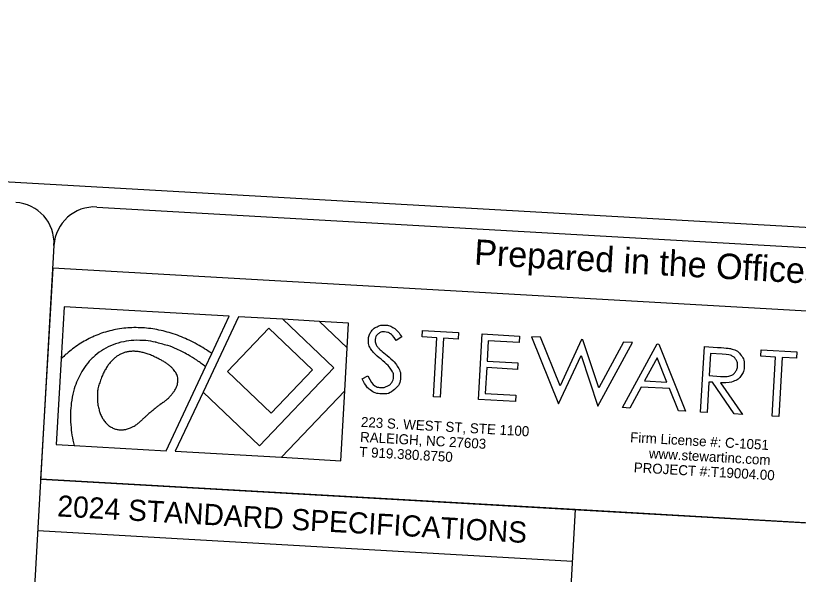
# Model space of a CAD drawing. Extents: x 2601627 to 2606907, y 616646 to 620530.
# Drawn here: x 2604538 to 2605115, y 617426 to 617838 of the extents above; entities that cross this region are included whole.
import ezdxf

# ---------------------------------------------------------------- set-up
doc = ezdxf.new("R2010")
doc.units = 0
doc.layers.add('Sheet Title CELL', color=7, linetype='Continuous')
doc.layers.add('Stewart Logo', color=7, linetype='Continuous')

msp = doc.modelspace()

# ---------------------------------------------------------------- linework, layer by layer
at = {"layer": 'Sheet Title CELL'}
for p, q in [((2602382.68, 617837.86), (2606635.79, 617595.63)), ((2604598.24, 617696.65), (2605451.86, 617648.03)), ((2604566.58, 617668.41), (2604539.29, 617189.18)), ((2604950.78, 617473.73), (2604556.77, 617496.18)), ((2604950.78, 617473.73), (2604931.59, 617136.79)), ((2605470.29, 617444.12), (2604950.78, 617473.73)), ((2604948.61, 617435.52), (2604554.6, 617458)), ((2604835.09, 617442.02), (2604835.09, 617442.02))]:
    msp.add_line(p, q, dxfattribs=at)
msp.add_lwpolyline([(2604556.77, 617496.18), (2605470.29, 617444.15), (2605479.15, 617599.69), (2604565.63, 617651.72)], close=True, dxfattribs=at)
for centre, start, end in [((2604536.65, 617670.24), 356.74026, 86.74026), ((2604596.55, 617666.83), 86.74026, 176.74026)]:
    msp.add_arc(centre, 30, start, end, dxfattribs=at)
at = {"layer": 'Stewart Logo'}
for p, q in [((2604574.08, 617623.18), (2604571.9, 617584.86)), ((2604695.75, 617616.25), (2604574.08, 617623.18)), ((2604702.53, 617615.87), (2604676.43, 617560.32)), ((2604682.83, 617588.75), (2604695.75, 617616.25)), ((2604735.34, 617614), (2604702.53, 617615.87)), ((2604735.34, 617614), (2604772.85, 617578.17)), ((2604762.32, 617612.46), (2604735.34, 617614)), ((2604772.85, 617578.17), (2604735.34, 617614)), ((2604783.73, 617611.24), (2604762.32, 617612.46)), ((2604762.32, 617612.46), (2604782.7, 617593)), ((2604782.7, 617593), (2604762.32, 617612.46)), ((2604782.7, 617593), (2604783.73, 617611.24)), ((2604600.3, 617603.21), (2604600.14, 617603.06)), ((2604606.3, 617605.1), (2604606.05, 617605.04)), ((2604642.37, 617606.42), (2604642.42, 617606.42)), ((2604641.35, 617597.05), (2604641.59, 617597.15)), ((2604925.07, 617600.76), (2604918.5, 617601.14)), ((2604918.5, 617601.14), (2604938.44, 617551.61)), ((2604939.5, 617565.07), (2604925.07, 617600.76)), ((2604955.38, 617599.04), (2604939.5, 617565.07)), ((2604956.32, 617598.98), (2604955.38, 617599.04)), ((2604968, 617563.45), (2604956.32, 617598.98)), ((2604967.45, 617549.96), (2604992.96, 617596.89)), ((2604986.39, 617597.27), (2604968, 617563.45)), ((2604992.96, 617596.89), (2604986.39, 617597.27)), ((2604672.08, 617595.55), (2604672.11, 617595.53)), ((2604780.89, 617561.22), (2604782.7, 617593)), ((2604678.25, 617578.99), (2604682.83, 617588.75)), ((2604938.44, 617551.61), (2604955.18, 617587.29)), ((2604955.18, 617587.29), (2604967.45, 617549.96)), ((2604571.9, 617584.86), (2604568.3, 617521.74)), ((2604649.19, 617517.14), (2604678.25, 617578.99)), ((2604772.85, 617578.17), (2604717.93, 617520.68)), ((2604717.93, 617520.68), (2604772.85, 617578.17)), ((2604726.61, 617544.85), (2604757.09, 617576.76)), ((2604676.43, 617560.32), (2604655.97, 617516.75)), ((2604717.93, 617520.68), (2604676.43, 617560.32)), ((2604676.43, 617560.32), (2604717.93, 617520.68)), ((2604780.89, 617561.22), (2604734.16, 617512.3)), ((2604734.16, 617512.3), (2604780.89, 617561.22)), ((2604777.96, 617509.8), (2604780.89, 617561.22)), ((2604568.3, 617521.74), (2604581.39, 617521)), ((2604581.39, 617521), (2604649.19, 617517.14)), ((2604655.97, 617516.75), (2604734.16, 617512.3)), ((2604734.16, 617512.3), (2604777.96, 617509.8))]:
    msp.add_line(p, q, dxfattribs=at)
for points in [[(2604694.56, 617575.46), (2604725.04, 617607.38), (2604757.09, 617576.76), (2604726.61, 617544.85), (2604694.56, 617575.46)], [(2604757.09, 617576.76), (2604725.04, 617607.38), (2604694.56, 617575.46), (2604726.61, 617544.85)], [(2604837.95, 617600.98), (2604838.22, 617605.71), (2604864.62, 617604.21), (2604864.35, 617599.48), (2604853.61, 617600.09), (2604851.13, 617556.59), (2604846.21, 617556.87), (2604848.69, 617600.37), (2604837.95, 617600.98)], [(2604882.07, 617603.21), (2604909.72, 617601.64), (2604909.45, 617596.91), (2604886.61, 617598.21), (2604885.75, 617583.1), (2604908.4, 617581.81), (2604908.13, 617577.08), (2604885.48, 617578.37), (2604884.4, 617559.43), (2604907.05, 617558.14), (2604906.78, 617553.42), (2604879.33, 617554.98), (2604882.07, 617603.21)], [(2604594.86, 617600.92), (2604595.3, 617601.13)], [(2604822.89, 617601.07), (2604818.79, 617598.31)], [(2604650.47, 617594.68), (2604650.22, 617594.58)], [(2605012.27, 617595.79), (2605032.02, 617546.28), (2605026.81, 617546.58), (2605020.14, 617562.91), (2604999.37, 617564.09), (2604990.96, 617548.62), (2604985.58, 617548.93), (2605011.1, 617595.86), (2605012.27, 617595.79)], [(2605057.88, 617567.26), (2605073.93, 617543.9), (2605067.96, 617544.24), (2605051.91, 617567.6), (2605049.19, 617567.76), (2605047.92, 617545.38), (2605043.12, 617545.65), (2605045.86, 617593.88)], [(2605045.86, 617593.88), (2605055.45, 617593.33)], [(2605087.46, 617586.77), (2605087.73, 617591.5), (2605114.13, 617589.99), (2605113.86, 617585.27), (2605103.12, 617585.88), (2605100.65, 617542.38), (2605095.73, 617542.66), (2605098.2, 617586.16), (2605087.46, 617586.77)], [(2604576.02, 617588.64), (2604575.67, 617588.43)], [(2605011.07, 617585.62), (2605001.82, 617568.61), (2605018.3, 617567.67), (2605011.07, 617585.62)], [(2605050.4, 617588.88), (2605049.46, 617572.48), (2605057.76, 617571.94)], [(2605058.9, 617588.4), (2605050.4, 617588.88)], [(2604793.66, 617570.09), (2604797.9, 617572.31)], [(2604645.62, 617551.77), (2604644.93, 617551.26)], [(2604646.67, 617552.5), (2604646.2, 617552.19)], [(2604647.41, 617552.9), (2604647.01, 617552.72)], [(2604632.86, 617541.2), (2604632.27, 617540.66)]]:
    msp.add_lwpolyline(points, dxfattribs=at)
for centre, radius, start, end in [((2604624.74, 617535), 72.37, 109.87286, 114.3888), ((2604624.74, 617535), 72.37, 109.87286, 114.3888), ((2604626.78, 617529.95), 77.91, 105.43457, 109.87286), ((2604626.78, 617529.95), 77.91, 105.43457, 109.87286), ((2604626.17, 617533.12), 74.68, 100.91778, 105.43457), ((2604626.17, 617533.12), 74.68, 100.91778, 105.43457), ((2604626.78, 617529.95), 77.91, 96.48359, 100.91778), ((2604626.78, 617529.95), 77.91, 96.48359, 100.91778), ((2604626.9, 617528.91), 78.95, 92.07873, 96.48359), ((2604626.9, 617528.91), 78.95, 92.07873, 96.48359), ((2604626.95, 617527.44), 80.42, 87.75387, 92.07873), ((2604626.95, 617527.44), 80.42, 87.75387, 92.07873), ((2604626.76, 617522.58), 85.28, 83.55429, 87.75387), ((2604626.76, 617522.58), 85.28, 83.55429, 87.75387), ((2604626.76, 617522.58), 85.28, 79.42201, 83.55429), ((2604626.76, 617522.58), 85.28, 79.42201, 83.55429), ((2604625.21, 617514.53), 93.48, 75.48982, 79.42201), ((2604625.21, 617514.53), 93.48, 75.48982, 79.42201), ((2604626.03, 617517.67), 90.24, 71.60319, 75.48982), ((2604626.03, 617517.67), 90.24, 71.60319, 75.48982), ((2604621.96, 617505.43), 103.14, 67.96772, 71.60319), ((2604621.96, 617505.43), 103.14, 67.96772, 71.60319), ((2604624.74, 617535), 72.37, 118.72075, 123.12292), ((2604624.74, 617535), 72.37, 118.72075, 123.12292), ((2604627.84, 617529.36), 78.81, 114.3888, 118.72075), ((2604627.84, 617529.36), 78.81, 114.3888, 118.72075), ((2604628.34, 617547.63), 50.94, 101.72957, 110.99727), ((2604628.34, 617547.63), 50.94, 101.72957, 110.99727), ((2604627.7, 617550.72), 47.78, 92.71006, 101.72957), ((2604627.7, 617550.72), 47.78, 92.71006, 101.72957), ((2604628.56, 617532.51), 66.01, 85.03885, 92.71006), ((2604628.56, 617532.51), 66.01, 85.03885, 92.71006), ((2604629.4, 617542.13), 56.35, 77.50343, 85.03885), ((2604629.4, 617542.13), 56.35, 77.50343, 85.03885), ((2604622.49, 617511.95), 87.17, 71.4501, 77.50343), ((2604622.49, 617511.95), 87.17, 71.4501, 77.50343), ((2604624.36, 617511.36), 96.74, 64.35062, 67.96772), ((2604624.36, 617511.36), 96.74, 64.35062, 67.96772), ((2604617.01, 617496.06), 113.71, 61.01445, 64.35062), ((2604617.01, 617496.06), 113.71, 61.01445, 64.35062), ((2604626.75, 617531.2), 76.64, 127.25223, 131.44668), ((2604626.75, 617531.2), 76.64, 127.25223, 131.44668), ((2604630.14, 617526.73), 82.24, 123.12292, 127.25223), ((2604630.14, 617526.73), 82.24, 123.12292, 127.25223), ((2604625.82, 617554), 44.08, 120.9119, 130.92188), ((2604625.82, 617554), 44.08, 120.9119, 130.92188), ((2604626.04, 617553.62), 44.52, 110.99727, 120.9119), ((2604626.04, 617553.62), 44.52, 110.99727, 120.9119), ((2604629.05, 617530.87), 67.31, 65.32215, 71.4501), ((2604629.05, 617530.87), 67.31, 65.32215, 71.4501), ((2604611.07, 617491.74), 110.38, 60.53753, 65.32215), ((2604611.07, 617491.74), 110.38, 60.53753, 65.32215), ((2604619.2, 617500.09), 109.13, 57.66813, 61.01445), ((2604619.2, 617500.09), 109.13, 57.66813, 61.01445), ((2604619.2, 617500.09), 109.13, 54.33197, 57.66813), ((2604619.2, 617500.09), 109.13, 54.33197, 57.66813), ((2604627.84, 617529.36), 78.81, 131.44668, 135.2248), ((2604627.84, 617529.36), 78.81, 131.44668, 135.2248), ((2604628.84, 617550.51), 48.7, 130.92188, 140.44427), ((2604628.84, 617550.51), 48.7, 130.92188, 140.44427), ((2604626.72, 617566.95), 24.12, 129.58941, 135.89408), ((2604626.72, 617566.95), 24.12, 129.58941, 135.89408), ((2604625.77, 617568.11), 22.62, 122.84002, 129.58941), ((2604625.77, 617568.11), 22.62, 122.84002, 129.58941), ((2604624.67, 617569.81), 20.59, 115.76574, 122.84002), ((2604624.67, 617569.81), 20.59, 115.76574, 122.84002), ((2604624.51, 617570.14), 20.23, 108.56755, 115.76574), ((2604624.51, 617570.14), 20.23, 108.56755, 115.76574), ((2604624.69, 617569.6), 20.8, 101.46827, 108.56756), ((2604624.69, 617569.6), 20.8, 101.46827, 108.56756), ((2604624.84, 617568.87), 21.54, 94.64152, 101.46827), ((2604624.84, 617568.87), 21.54, 94.64152, 101.46827), ((2604625.1, 617565.63), 24.8, 88.27953, 94.64152), ((2604625.1, 617565.63), 24.8, 88.27953, 94.64152), ((2604625.04, 617563.72), 26.71, 82.42228, 88.27953), ((2604625.04, 617563.72), 26.71, 82.42228, 88.27953), ((2604624.19, 617557.31), 33.17, 77.16679, 82.42228), ((2604624.19, 617557.31), 33.17, 77.16679, 82.42228), ((2604623.48, 617554.19), 36.37, 72.43685, 77.16679), ((2604623.48, 617554.19), 36.37, 72.43685, 77.16679), ((2604620.32, 617544.22), 46.83, 68.26897, 72.43685), ((2604620.32, 617544.22), 46.83, 68.26897, 72.43685), ((2604616.17, 617533.79), 58.05, 64.53971, 68.26896), ((2604616.17, 617533.79), 58.05, 64.53971, 68.26896), ((2604621.14, 617544.24), 46.48, 60.37182, 64.53971), ((2604621.14, 617544.24), 46.48, 60.37182, 64.53971), ((2604622.49, 617511.95), 87.17, 55.51815, 60.53753), ((2604622.49, 617511.95), 87.17, 55.51815, 60.53753), ((2604626.01, 617552.84), 45.03, 140.44427, 149.84218), ((2604626.01, 617552.84), 45.03, 140.44427, 149.84218), ((2604632.47, 617561.77), 31.87, 141.63478, 146.83116), ((2604632.47, 617561.77), 31.87, 141.63478, 146.83116), ((2604630.29, 617563.49), 29.09, 135.89408, 141.63478), ((2604630.29, 617563.49), 29.09, 135.89408, 141.63478), ((2604628.45, 617551.75), 36.44, 60.64199, 64.52966), ((2604628.45, 617551.75), 36.44, 60.64199, 64.52966), ((2604622.87, 617541.82), 47.83, 57.24889, 60.64199), ((2604622.87, 617541.82), 47.83, 57.24889, 60.64199), ((2604628.84, 617551.11), 36.79, 53.36122, 57.24889), ((2604628.84, 617551.11), 36.79, 53.36122, 57.24889), ((2604634.73, 617559.03), 26.91, 48.81551, 53.36122), ((2604634.73, 617559.03), 26.91, 48.81551, 53.36122), ((2604617.53, 617504.73), 95.92, 50.73353, 55.51815), ((2604617.53, 617504.73), 95.92, 50.73353, 55.51815), ((2604639.9, 617544.78), 61.09, 149.84218, 157.90863), ((2604639.9, 617544.78), 61.09, 149.84218, 157.90863), ((2604643.34, 617555.07), 44.65, 151.44194, 155.56555), ((2604643.34, 617555.07), 44.65, 151.44194, 155.56555), ((2604639.67, 617557.06), 40.47, 146.83116, 151.44194), ((2604639.67, 617557.06), 40.47, 146.83116, 151.44194), ((2604636.85, 617561.45), 23.69, 43.58421, 48.81551), ((2604636.85, 617561.45), 23.69, 43.58421, 48.81551), ((2604641.26, 617565.64), 17.62, 37.51656, 43.58421), ((2604641.26, 617565.64), 17.62, 37.51656, 43.58421), ((2604642.81, 617566.84), 15.65, 30.63591, 37.51656), ((2604642.81, 617566.84), 15.65, 30.63591, 37.51656), ((2604645.54, 617568.46), 12.48, 22.92801, 30.63591), ((2604645.54, 617568.46), 12.48, 22.92801, 30.63591), ((2604668.14, 617544.75), 71.52, 159.18991, 162.4335), ((2604668.14, 617544.75), 71.52, 159.18991, 162.4335), ((2604655.3, 617549.63), 57.79, 155.56556, 159.18991), ((2604655.3, 617549.63), 57.79, 155.56556, 159.18991), ((2604646.37, 617568.81), 11.58, 14.59915, 22.928), ((2604646.37, 617568.81), 11.58, 14.59915, 22.928), ((2604647.28, 617569.04), 10.65, 5.91086, 14.59915), ((2604647.28, 617569.04), 10.65, 5.91086, 14.59915), ((2604646.19, 617569.09), 11.74, 348.98416, 357.24672), ((2604646.19, 617569.09), 11.74, 348.98416, 357.24672), ((2604647.25, 617569.04), 10.68, 357.24673, 5.91085), ((2604647.25, 617569.04), 10.68, 357.24673, 5.91085), ((2604631.4, 617548.22), 51.92, 157.90863, 165.86768), ((2604631.4, 617548.22), 51.92, 157.90863, 165.86768), ((2604640.43, 617556.8), 41.9, 171.69807, 175.85224), ((2604640.43, 617556.8), 41.9, 171.69807, 175.85224), ((2604654.57, 617549.05), 57.29, 162.4335, 166.05786), ((2604654.57, 617549.05), 57.29, 162.4335, 166.05786), ((2604640.24, 617571.21), 18.07, 328.63045, 334.5943), ((2604640.24, 617571.21), 18.07, 328.63045, 334.5943), ((2604642.09, 617570.34), 16.03, 334.59429, 341.37021), ((2604642.09, 617570.34), 16.03, 334.59429, 341.37021), ((2604645.24, 617569.27), 12.7, 341.37021, 348.98416), ((2604645.24, 617569.27), 12.7, 341.37021, 348.98416), ((2604658.94, 617541.29), 80.31, 165.86768, 172.2653), ((2604658.94, 617541.29), 80.31, 165.86768, 172.2653), ((2604635.98, 617557.12), 37.44, 175.85223, 180.24696), ((2604635.98, 617557.12), 37.44, 175.85223, 180.24696), ((2604646.85, 617557.17), 48.31, 180.24695, 184.40112), ((2604646.85, 617557.17), 48.31, 180.24695, 184.40112), ((2604616.54, 617591.06), 49.1, 311.88114, 315.2142), ((2604616.54, 617591.06), 49.1, 311.88114, 315.2142), ((2604624.55, 617583.11), 37.81, 315.2142, 319.03129), ((2604624.55, 617583.11), 37.81, 315.2142, 319.03129), ((2604632.21, 617576.46), 27.67, 319.03129, 323.49364), ((2604632.21, 617576.46), 27.67, 319.03129, 323.49364), ((2604634.88, 617574.48), 24.36, 323.49364, 328.63045), ((2604634.88, 617574.48), 24.36, 323.49364, 328.63045), ((2604640.88, 617543.74), 62.1, 172.2653, 178.72703), ((2604640.88, 617543.74), 62.1, 172.2653, 178.72703), ((2604628.35, 617555.75), 29.75, 184.40113, 189.69526), ((2604628.35, 617555.75), 29.75, 184.40113, 189.69526), ((2604637.07, 617557.24), 38.6, 189.69526, 194.92379), ((2604637.07, 617557.24), 38.6, 189.69526, 194.92379), ((2604697.35, 617481.51), 87.26, 126.9285, 127.60484), ((2604697.35, 617481.51), 87.26, 126.9285, 127.60484), ((2604676.52, 617509.23), 52.58, 125.98914, 126.9285), ((2604667.07, 617522.24), 36.5, 124.86162, 125.98916), ((2604667.07, 617522.24), 36.5, 124.86162, 125.98916), ((2604656.13, 617537.94), 17.36, 123.01394, 124.86163), ((2604651.61, 617544.9), 9.07, 120.45773, 123.01391), ((2604651.61, 617544.9), 9.07, 120.45773, 123.01391), ((2604647.71, 617551.53), 1.38, 114.8005, 120.45777), ((2604649.96, 617546.66), 6.74, 112.24433, 114.80057), ((2604624.32, 617582.38), 37.44, 308.06404, 311.88113), ((2604624.32, 617582.38), 37.44, 308.06404, 311.88113), ((2604681.44, 617542.84), 102.66, 178.72703, 183.75142), ((2604681.44, 617542.84), 102.66, 178.72703, 183.75142), ((2604623.53, 617553.63), 24.59, 194.9238, 201.47591), ((2604623.53, 617553.63), 24.59, 194.9238, 201.47591), ((2604804.91, 617348.18), 258.58, 130.27656, 130.61616), ((2604804.91, 617348.18), 258.58, 130.27656, 130.61616), ((2604778.17, 617379.73), 217.23, 129.90605, 130.27656), ((2604778.17, 617379.73), 217.23, 129.90605, 130.27656), ((2604792.5, 617362.59), 239.56, 129.53731, 129.90605), ((2604792.5, 617362.59), 239.56, 129.53731, 129.90605), ((2604767.52, 617392.85), 200.33, 129.13408, 129.53731), ((2604767.52, 617392.85), 200.33, 129.13408, 129.53731), ((2604756.24, 617406.73), 182.44, 128.69132, 129.13408), ((2604756.24, 617406.73), 182.44, 128.69132, 129.13408), ((2604735.94, 617432.06), 149.98, 128.20299, 128.69131), ((2604735.94, 617432.06), 149.98, 128.20299, 128.69131), ((2604712.18, 617462.25), 111.56, 127.60484, 128.20299), ((2604712.18, 617462.25), 111.56, 127.60484, 128.20299), ((2604627.05, 617555.01), 28.37, 201.47591, 208.25005), ((2604627.05, 617555.01), 28.37, 201.47591, 208.25005), ((2604619.22, 617550.81), 19.48, 208.25005, 216.42587), ((2604619.22, 617550.81), 19.48, 208.25005, 216.42587), ((2604619.63, 617551.11), 19.99, 216.42587, 225.14858), ((2604619.63, 617551.11), 19.99, 216.42587, 225.14858), ((2604611.96, 617558.62), 27.03, 310.79658, 316.40196), ((2604611.96, 617558.62), 27.03, 310.79658, 316.40196), ((2604736.04, 617427.74), 153.36, 132.58163, 132.95594), ((2604736.04, 617427.74), 153.36, 132.58163, 132.95594), ((2604697.51, 617469.67), 96.41, 132.10955, 132.58164), ((2604753.65, 617407.57), 180.13, 131.73525, 132.10956), ((2604753.65, 617407.57), 180.13, 131.73525, 132.10956), ((2604736.37, 617426.93), 154.18, 131.33067, 131.73525), ((2604736.37, 617426.93), 154.18, 131.33067, 131.73525), ((2604788.95, 617367.14), 233.8, 130.98852, 131.33067), ((2604788.95, 617367.14), 233.8, 130.98852, 131.33067), ((2604765.07, 617394.63), 197.39, 130.61616, 130.98852), ((2604765.07, 617394.63), 197.39, 130.61616, 130.98852), ((2604660.84, 617541.49), 82.02, 183.75142, 188.99425), ((2604660.84, 617541.49), 82.02, 183.75142, 188.99425), ((2604616.76, 617548.23), 15.93, 225.14857, 234.92377), ((2604616.76, 617548.23), 15.93, 225.14857, 234.92377), ((2604616.21, 617547.44), 14.96, 234.92377, 245.30825), ((2604616.21, 617547.44), 14.96, 234.92377, 245.30825), ((2604616.25, 617547.53), 15.06, 245.30825, 255.65854), ((2604616.25, 617547.53), 15.06, 245.30825, 255.65854), ((2604614.25, 617555.31), 23.06, 284.75007, 292.11877), ((2604614.25, 617555.31), 23.06, 284.75007, 292.11877), ((2604616.12, 617550.7), 18.08, 292.11877, 299.46011), ((2604616.12, 617550.7), 18.08, 292.11877, 299.46011), ((2604609.77, 617561.95), 31, 299.46011, 305.06549), ((2604609.77, 617561.95), 31, 299.46011, 305.06549), ((2604612.73, 617557.74), 25.86, 305.06549, 310.79658), ((2604612.73, 617557.74), 25.86, 305.06549, 310.79658), ((2604668.03, 617542.63), 89.3, 188.99425, 194.01864), ((2604668.03, 617542.63), 89.3, 188.99425, 194.01864), ((2604615.84, 617545.94), 13.42, 255.65854, 266.24906), ((2604615.84, 617545.94), 13.42, 255.65854, 266.24906), ((2604616.11, 617549.96), 17.45, 266.24906, 275.53273), ((2604616.11, 617549.96), 17.45, 266.24906, 275.53273), ((2604616.37, 617547.27), 14.75, 275.53273, 284.75007), ((2604616.37, 617547.27), 14.75, 275.53273, 284.75007)]:
    msp.add_arc(centre, radius, start, end, dxfattribs=at)
for points in [[(2604797.9, 617572.31), (2604801.77, 617564.1), (2604807.44, 617563.78), (2604809.86, 617563.64), (2604812.06, 617564.65), (2604814.25, 617565.66), (2604815.47, 617567.5), (2604816.69, 617569.33), (2604816.82, 617571.46), (2604816.95, 617573.89), (2604815.45, 617576.31), (2604813.37, 617579.65), (2604807.63, 617584.51), (2604801.86, 617589.41), (2604800.5, 617591.53), (2604798.14, 617595.09), (2604798.37, 617599.06), (2604798.55, 617602.2), (2604800.2, 617604.71), (2604801.85, 617607.22), (2604804.67, 617608.55), (2604807.49, 617609.89), (2604810.7, 617609.71), (2604814.11, 617609.51), (2604816.97, 617607.65), (2604819.84, 617605.79), (2604822.89, 617601.07)], [(2604818.79, 617598.31), (2604816.27, 617602.07), (2604814.42, 617603.33), (2604812.57, 617604.58), (2604810.31, 617604.71), (2604807.39, 617604.88), (2604805.44, 617603.22), (2604803.49, 617601.55), (2604803.34, 617598.96), (2604803.25, 617597.39), (2604803.82, 617595.88), (2604804.39, 617594.37), (2604806.03, 617592.53), (2604806.93, 617591.56), (2604811.98, 617587.36), (2604817.98, 617582.38), (2604820.1, 617578.64), (2604822.22, 617574.9), (2604822.02, 617571.27), (2604821.72, 617566.02), (2604817.52, 617562.38), (2604813.32, 617558.74), (2604807.62, 617559.07), (2604803.23, 617559.32), (2604799.8, 617561.86), (2604796.36, 617564.41), (2604793.66, 617570.09)], [(2605055.45, 617593.33), (2605063.47, 617592.88), (2605066.28, 617592.06), (2605070.51, 617590.83), (2605073.01, 617587.44), (2605075.51, 617584.05), (2605075.24, 617579.32), (2605075.02, 617575.38), (2605073, 617572.5), (2605070.98, 617569.61), (2605067.45, 617568.28), (2605063.93, 617566.95), (2605057.88, 617567.26)], [(2605057.76, 617571.94), (2605062.59, 617571.67), (2605064.95, 617572.45), (2605067.32, 617573.24), (2605068.73, 617575.18), (2605070.14, 617577.13), (2605070.28, 617579.62), (2605070.42, 617582.05), (2605069.22, 617584.11), (2605068.02, 617586.17), (2605065.94, 617587.14), (2605063.85, 617588.12), (2605058.9, 617588.4)]]:
    msp.add_open_spline(points, degree=3, dxfattribs=at)

# ---------------------------------------------------------------- texts
at = {"layer": 'Sheet Title CELL'}
for s, height, p in [('Prepared in the Offices of:', 18.75, (2604875.93, 617654.34)), ('2024 STANDARD SPECIFICATIONS', 15.5999, (2604568.7, 617468.76))]:
    msp.add_text(s, height=height, rotation=356.74026, dxfattribs=at).set_placement(p)
at = {"layer": 'Stewart Logo'}
for s, p in [('223 S. WEST ST, STE 1100', (2604792.64, 617534.77)), ('RALEIGH, NC 27603', (2604792.02, 617523.75)), ('Firm License #: C-1051', (2604991.04, 617523.47)), ('T 919.380.8750', (2604791.39, 617512.73)), ('www.stewartinc.com', (2605004.86, 617511.63)), ('PROJECT #:T19004.00', (2604993.71, 617501.2))]:
    msp.add_text(s, height=7.3611, rotation=356.73977, dxfattribs=at).set_placement(p)

doc.saveas('drawing.dxf')
